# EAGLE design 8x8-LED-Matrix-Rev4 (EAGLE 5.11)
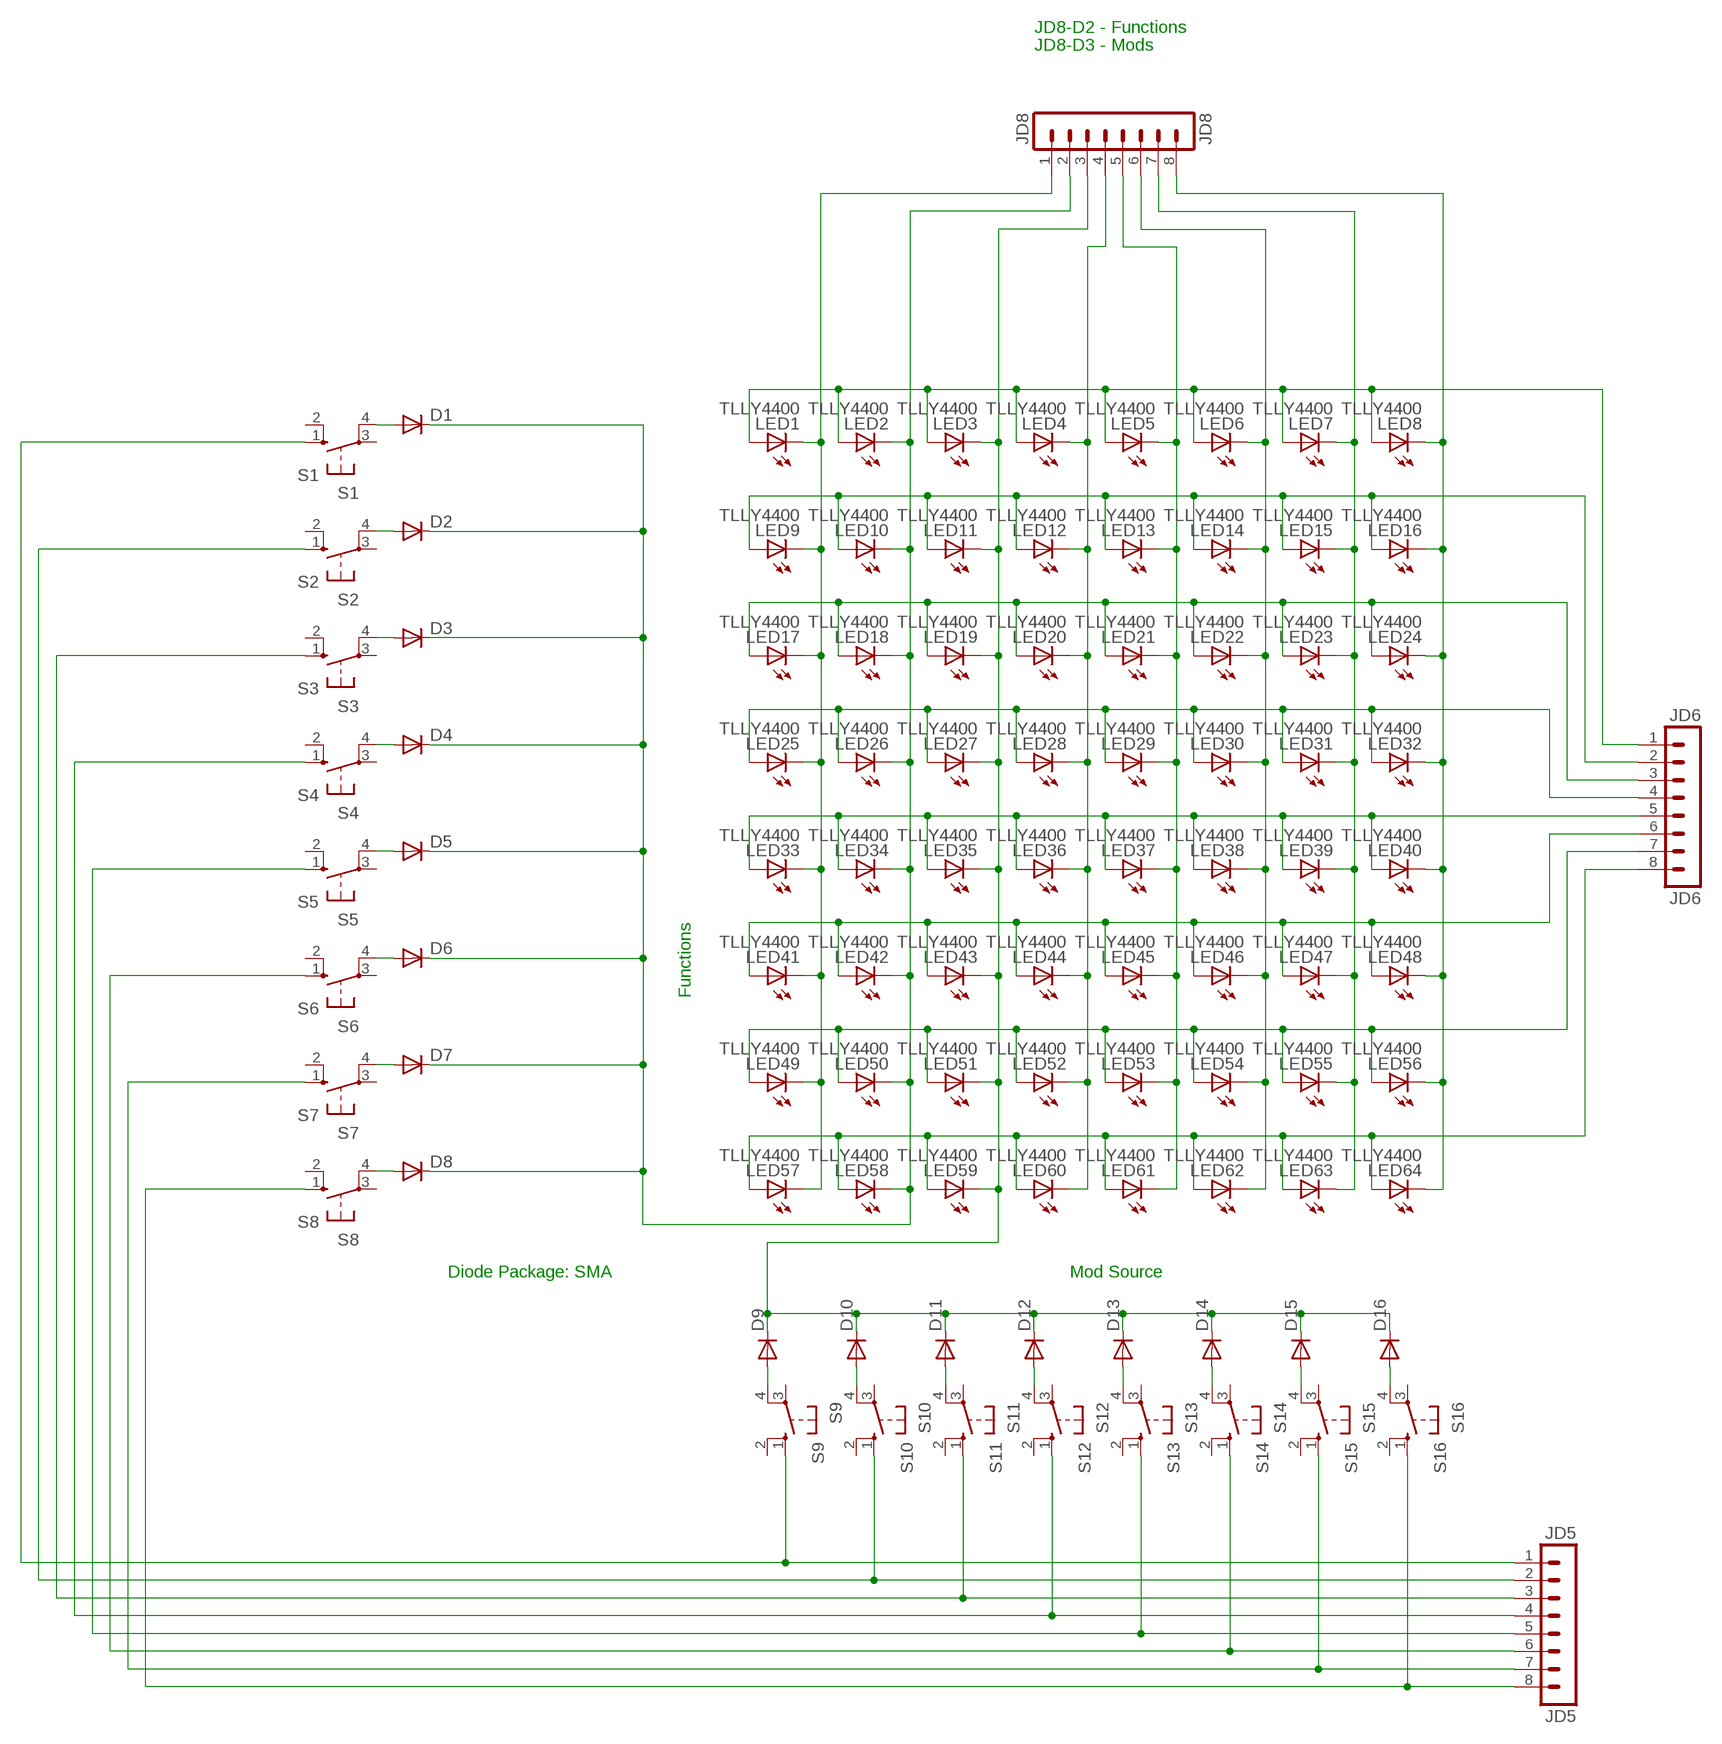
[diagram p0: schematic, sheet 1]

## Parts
D1  DIODE-DO214AC  [DO214AC]
D2  DIODE-DO214AC  [DO214AC]
D3  DIODE-DO214AC  [DO214AC]
D4  DIODE-DO214AC  [DO214AC]
D5  DIODE-DO214AC  [DO214AC]
D6  DIODE-DO214AC  [DO214AC]
D7  DIODE-DO214AC  [DO214AC]
D8  DIODE-DO214AC  [DO214AC]
D9  DIODE-DO214AC  [DO214AC]
D10  DIODE-DO214AC  [DO214AC]
D11  DIODE-DO214AC  [DO214AC]
D12  DIODE-DO214AC  [DO214AC]
D13  DIODE-DO214AC  [DO214AC]
D14  DIODE-DO214AC  [DO214AC]
D15  DIODE-DO214AC  [DO214AC]
D16  DIODE-DO214AC  [DO214AC]
JD5  JD5  MA08-1  [MA08-1]
JD6  JD6  MA08-1  [MA08-1]
JD8  JD8  MA08-1  [MA08-1]
LED1  TLLY4400  [LED3MM]
LED2  TLLY4400  [LED3MM]
LED3  TLLY4400  [LED3MM]
LED4  TLLY4400  [LED3MM]
LED5  TLLY4400  [LED3MM]
LED6  TLLY4400  [LED3MM]
LED7  TLLY4400  [LED3MM]
LED8  TLLY4400  [LED3MM]
LED9  TLLY4400  [LED3MM]
LED10  TLLY4400  [LED3MM]
LED11  TLLY4400  [LED3MM]
LED12  TLLY4400  [LED3MM]
LED13  TLLY4400  [LED3MM]
LED14  TLLY4400  [LED3MM]
LED15  TLLY4400  [LED3MM]
LED16  TLLY4400  [LED3MM]
LED17  TLLY4400  [LED3MM]
LED18  TLLY4400  [LED3MM]
LED19  TLLY4400  [LED3MM]
LED20  TLLY4400  [LED3MM]
LED21  TLLY4400  [LED3MM]
LED22  TLLY4400  [LED3MM]
LED23  TLLY4400  [LED3MM]
LED24  TLLY4400  [LED3MM]
LED25  TLLY4400  [LED3MM]
LED26  TLLY4400  [LED3MM]
LED27  TLLY4400  [LED3MM]
LED28  TLLY4400  [LED3MM]
LED29  TLLY4400  [LED3MM]
LED30  TLLY4400  [LED3MM]
LED31  TLLY4400  [LED3MM]
LED32  TLLY4400  [LED3MM]
LED33  TLLY4400  [LED3MM]
LED34  TLLY4400  [LED3MM]
LED35  TLLY4400  [LED3MM]
LED36  TLLY4400  [LED3MM]
LED37  TLLY4400  [LED3MM]
LED38  TLLY4400  [LED3MM]
LED39  TLLY4400  [LED3MM]
LED40  TLLY4400  [LED3MM]
LED41  TLLY4400  [LED3MM]
LED42  TLLY4400  [LED3MM]
LED43  TLLY4400  [LED3MM]
LED44  TLLY4400  [LED3MM]
LED45  TLLY4400  [LED3MM]
LED46  TLLY4400  [LED3MM]
LED47  TLLY4400  [LED3MM]
LED48  TLLY4400  [LED3MM]
LED49  TLLY4400  [LED3MM]
LED50  TLLY4400  [LED3MM]
LED51  TLLY4400  [LED3MM]
LED52  TLLY4400  [LED3MM]
LED53  TLLY4400  [LED3MM]
LED54  TLLY4400  [LED3MM]
LED55  TLLY4400  [LED3MM]
LED56  TLLY4400  [LED3MM]
LED57  TLLY4400  [LED3MM]
LED58  TLLY4400  [LED3MM]
LED59  TLLY4400  [LED3MM]
LED60  TLLY4400  [LED3MM]
LED61  TLLY4400  [LED3MM]
LED62  TLLY4400  [LED3MM]
LED63  TLLY4400  [LED3MM]
LED64  TLLY4400  [LED3MM]
S1  S1  10-XX  [B3F-10XX]
S2  S2  10-XX  [B3F-10XX]
S3  S3  10-XX  [B3F-10XX]
S4  S4  10-XX  [B3F-10XX]
S5  S5  10-XX  [B3F-10XX]
S6  S6  10-XX  [B3F-10XX]
S7  S7  10-XX  [B3F-10XX]
S8  S8  10-XX  [B3F-10XX]
S9  S9  10-XX  [B3F-10XX]
S10  S10  10-XX  [B3F-10XX]
S11  S11  10-XX  [B3F-10XX]
S12  S12  10-XX  [B3F-10XX]
S13  S13  10-XX  [B3F-10XX]
S14  S14  10-XX  [B3F-10XX]
S15  S15  10-XX  [B3F-10XX]
S16  S16  10-XX  [B3F-10XX]

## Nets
N$1: JD6.1 LED1.A LED2.A LED3.A LED4.A LED5.A LED6.A LED7.A LED8.A
N$2: JD6.2 LED9.A LED10.A LED11.A LED12.A LED13.A LED14.A LED15.A LED16.A
N$3: JD6.3 LED17.A LED18.A LED19.A LED20.A LED21.A LED22.A LED23.A LED24.A
N$4: JD6.4 LED25.A LED26.A LED27.A LED28.A LED29.A LED30.A LED31.A LED32.A
N$5: JD6.5 LED33.A LED34.A LED35.A LED36.A LED37.A LED38.A LED39.A LED40.A
N$6: JD6.6 LED41.A LED42.A LED43.A LED44.A LED45.A LED46.A LED47.A LED48.A
N$7: D1.A S1.4(P1)
N$8: JD6.8 LED57.A LED58.A LED59.A LED60.A LED61.A LED62.A LED63.A LED64.A
N$9: JD8.1 LED1.K(C) LED9.K(C) LED17.K(C) LED25.K(C) LED33.K(C) LED41.K(C) LED49.K(C) LED57.K(C)
N$10: D1.C D2.C D3.C D4.C D5.C D6.C D7.C D8.C JD8.2 LED2.K(C) LED10.K(C) LED18.K(C) LED26.K(C) LED34.K(C) LED42.K(C) LED50.K(C) LED58.K(C)
N$11: D2.A S2.4(P1)
N$12: JD8.4 LED4.K(C) LED12.K(C) LED20.K(C) LED28.K(C) LED36.K(C) LED44.K(C) LED52.K(C) LED60.K(C)
N$13: JD8.5 LED5.K(C) LED13.K(C) LED21.K(C) LED29.K(C) LED37.K(C) LED45.K(C) LED53.K(C) LED61.K(C)
N$14: JD8.6 LED6.K(C) LED14.K(C) LED22.K(C) LED30.K(C) LED38.K(C) LED46.K(C) LED54.K(C) LED62.K(C)
N$15: JD8.7 LED7.K(C) LED15.K(C) LED23.K(C) LED31.K(C) LED39.K(C) LED47.K(C) LED55.K(C) LED63.K(C)
N$16: JD8.8 LED8.K(C) LED16.K(C) LED24.K(C) LED32.K(C) LED40.K(C) LED48.K(C) LED56.K(C) LED64.K(C)
N$17: JD6.7 LED49.A LED50.A LED51.A LED52.A LED53.A LED54.A LED55.A LED56.A
N$18: JD5.1 S1.1(S) S9.1(S)
N$19: JD5.2 S2.1(S) S10.1(S)
N$20: JD5.4 S4.1(S) S12.1(S)
N$21: JD5.5 S5.1(S) S13.1(S)
N$22: JD5.6 S6.1(S) S14.1(S)
N$23: JD5.7 S7.1(S) S15.1(S)
N$24: JD5.8 S8.1(S) S16.1(S)
N$25: JD5.3 S3.1(S) S11.1(S)
N$26: D3.A S3.4(P1)
N$27: D4.A S4.4(P1)
N$28: D5.A S5.4(P1)
N$29: D6.A S6.4(P1)
N$30: D7.A S7.4(P1)
N$31: D9.C D10.C D11.C D12.C D13.C D14.C D15.C D16.C JD8.3 LED3.K(C) LED11.K(C) LED19.K(C) LED27.K(C) LED35.K(C) LED43.K(C) LED51.K(C) LED59.K(C)
N$32: D9.A S9.4(P1)
N$33: D10.A S10.4(P1)
N$34: D8.A S8.4(P1)
N$35: D11.A S11.4(P1)
N$36: D12.A S12.4(P1)
N$37: D13.A S13.4(P1)
N$38: D14.A S14.4(P1)
N$39: D15.A S15.4(P1)
N$40: D16.A S16.4(P1)
Unconnected: S1.2(S1) S1.3(P) S2.2(S1) S2.3(P) S3.2(S1) S3.3(P) S4.2(S1) S4.3(P) S5.2(S1) S5.3(P) S6.2(S1) S6.3(P) S7.2(S1) S7.3(P) S8.2(S1) S8.3(P) S9.2(S1) S9.3(P) S10.2(S1) S10.3(P) S11.2(S1) S11.3(P) S12.2(S1) S12.3(P) S13.2(S1) S13.3(P) S14.2(S1) S14.3(P) S15.2(S1) S15.3(P) S16.2(S1) S16.3(P)

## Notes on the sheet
- JD8-D2 - Functions
- JD8-D3 - Mods
- Functions
- Diode Package: SMA | Mod Source

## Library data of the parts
D1-D16 = diode:DIODE-: DIODE
JD5 JD6 JD8 = con-lstb:MA08-1: PIN HEADER; OC_FARNELL: unknown; OC_NEWARK: unknown
LED1-LED64 = led:TLLY4400: Low Current (2mA) LED 3 mm Tinted Diffused Package color YELLOW; MF: VISHAY SEMICONDUCTOR; OC_FARNELL: 1612439
S1-S16 = switch-omron:10-XX: OMRON SWITCH; MPN: B3F-1000; OC_FARNELL: 176432; OC_NEWARK: 36M3542

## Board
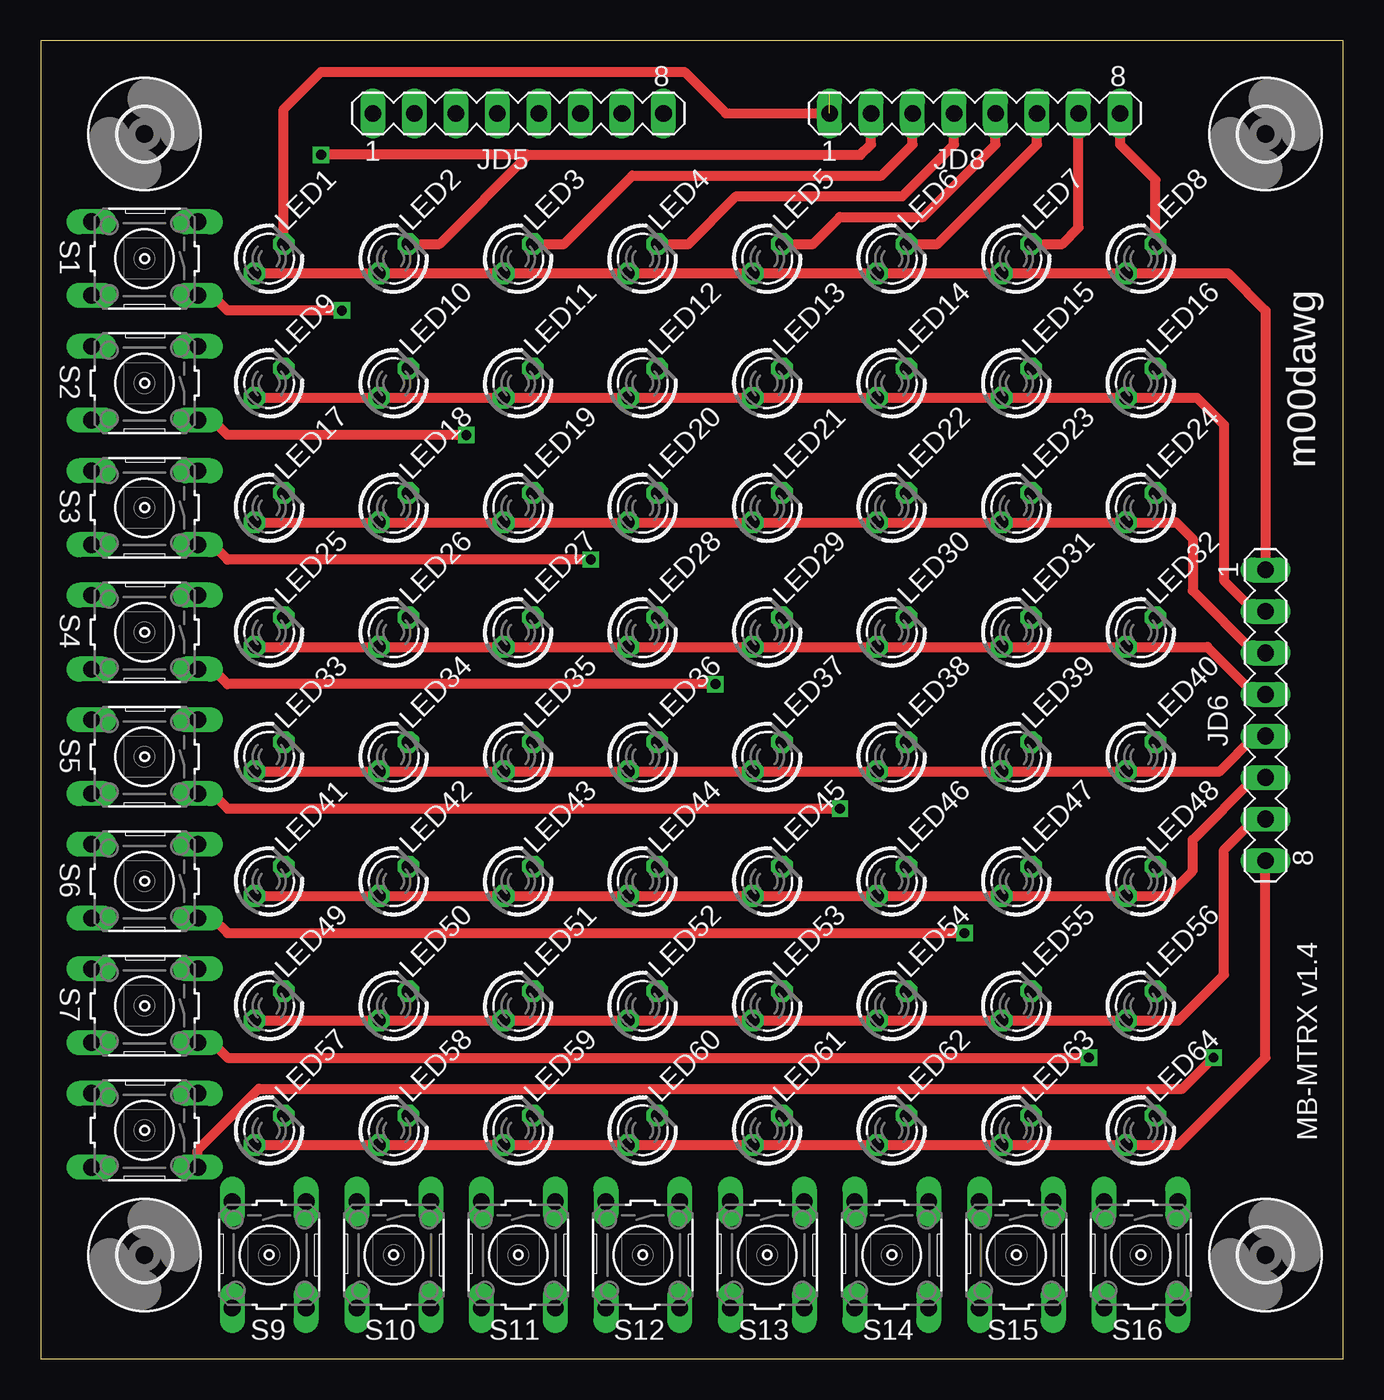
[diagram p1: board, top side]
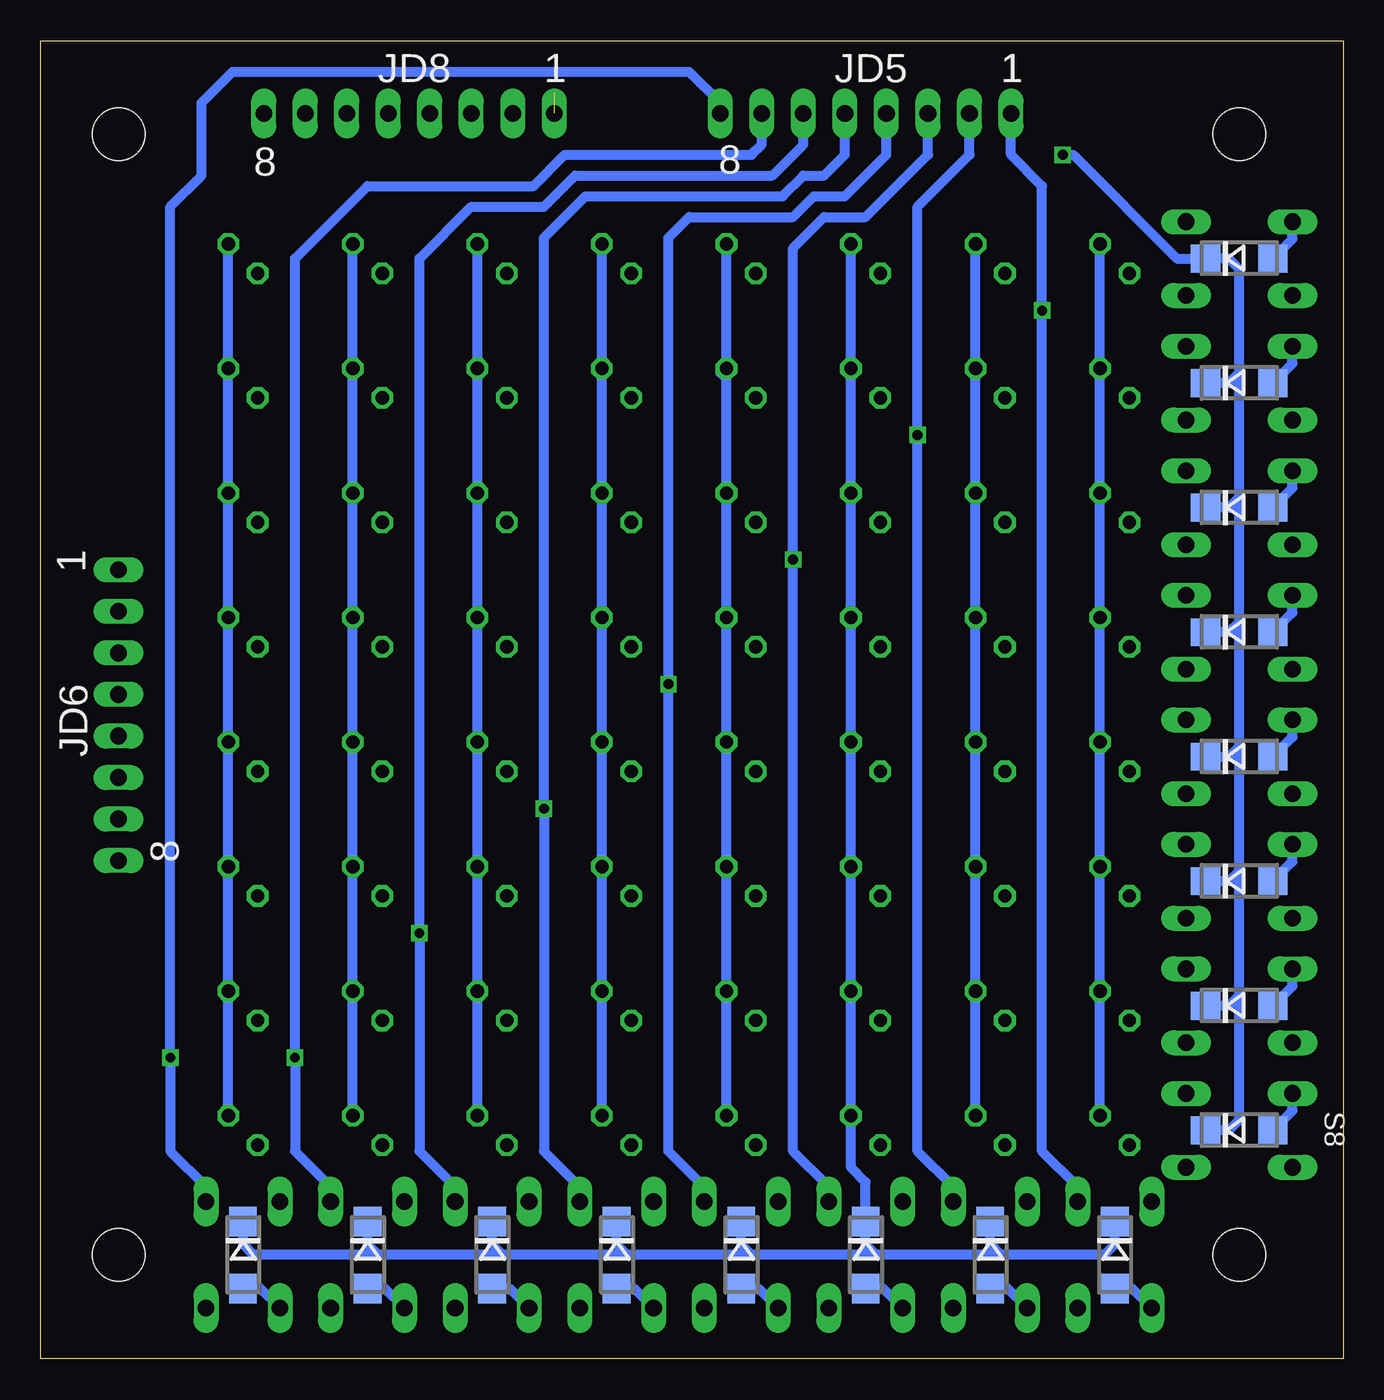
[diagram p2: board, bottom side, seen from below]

Size 79.68 x 80.64 mm. Coordinates in mm from the lower left corner, seen from the top.
Outline: 0,0 79.68,0 79.68,80.64 0,80.64 0,0
Copper layers (1*16): Top 0.035mm / dielectric 1.5mm / Bottom 0.035mm
Design rules "batchpcb": minimum track width 8mil, minimum drill 20mil, track to track 8mil, track to pad 8mil, pad to pad 8mil, via to via 8mil, smd to smd 8mil, copper to edge 40mil, drill to drill 8mil, minimum pad ring 10mil, minimum via ring 8mil, stop-mask expansion 4mil, vias tented up to drill 0mil, thermal gap 10mil

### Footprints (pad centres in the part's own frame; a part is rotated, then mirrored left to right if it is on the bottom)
DO214AC = smd 1.8 x 1.7: A 2.05,0; C -2.05,0
MA08-1 = drill 1.016 long: 1 -8.89,0; 2 -6.35,0; 3 -3.81,0; 4 -1.27,0; 5 1.27,0; 6 3.81,0; 7 6.35,0; 8 8.89,0
LED3MM = drill 0.813 octagon: A -1.27,0; K 1.27,0
B3F-10XX = drill 1.016 long: 1 -3.251,2.261; 2 3.251,2.261; 3 -3.251,-2.261; 4 3.251,-2.261
3,2 = hole 3.2: 0,0

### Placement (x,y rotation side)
D1  6.35,67.31 0 bottom
D2  6.35,59.69 0 bottom
D3  6.35,52.07 0 bottom
D4  6.35,44.45 0 bottom
D5  6.35,36.83 0 bottom
D6  6.35,29.21 0 bottom
D7  6.35,21.59 0 bottom
D8  6.35,13.97 0 bottom
D9  13.97,6.35 270 bottom
D10  21.59,6.35 270 bottom
D11  29.21,6.35 270 bottom
D12  36.83,6.35 270 bottom
D13  44.45,6.35 270 bottom
D14  52.07,6.35 270 bottom
D15  59.69,6.35 270 bottom
D16  67.31,6.35 270 bottom
JD5  29.21,76.2 0 top
JD6  74.93,39.37 270 top
JD8  57.15,76.2 0 top
LED1  13.97,67.31 45 top
LED2  21.59,67.31 45 top
LED3  29.21,67.31 45 top
LED4  36.83,67.31 45 top
LED5  44.45,67.31 45 top
LED6  52.07,67.31 45 top
LED7  59.69,67.31 45 top
LED8  67.31,67.31 45 top
LED9  13.97,59.69 45 top
LED10  21.59,59.69 45 top
LED11  29.21,59.69 45 top
LED12  36.83,59.69 45 top
LED13  44.45,59.69 45 top
LED14  52.07,59.69 45 top
LED15  59.69,59.69 45 top
LED16  67.31,59.69 45 top
LED17  13.97,52.07 45 top
LED18  21.59,52.07 45 top
LED19  29.21,52.07 45 top
LED20  36.83,52.07 45 top
LED21  44.45,52.07 45 top
LED22  52.07,52.07 45 top
LED23  59.69,52.07 45 top
LED24  67.31,52.07 45 top
LED25  13.97,44.45 45 top
LED26  21.59,44.45 45 top
LED27  29.21,44.45 45 top
LED28  36.83,44.45 45 top
LED29  44.45,44.45 45 top
LED30  52.07,44.45 45 top
LED31  59.69,44.45 45 top
LED32  67.31,44.45 45 top
LED33  13.97,36.83 45 top
LED34  21.59,36.83 45 top
LED35  29.21,36.83 45 top
LED36  36.83,36.83 45 top
LED37  44.45,36.83 45 top
LED38  52.07,36.83 45 top
LED39  59.69,36.83 45 top
LED40  67.31,36.83 45 top
LED41  13.97,29.21 45 top
LED42  21.59,29.21 45 top
LED43  29.21,29.21 45 top
LED44  36.83,29.21 45 top
LED45  44.45,29.21 45 top
LED46  52.07,29.21 45 top
LED47  59.69,29.21 45 top
LED48  67.31,29.21 45 top
LED49  13.97,21.59 45 top
LED50  21.59,21.59 45 top
LED51  29.21,21.59 45 top
LED52  36.83,21.59 45 top
LED53  44.45,21.59 45 top
LED54  52.07,21.59 45 top
LED55  59.69,21.59 45 top
LED56  67.31,21.59 45 top
LED57  13.97,13.97 45 top
LED58  21.59,13.97 45 top
LED59  29.21,13.97 45 top
LED60  36.83,13.97 45 top
LED61  44.45,13.97 45 top
LED62  52.07,13.97 45 top
LED63  59.69,13.97 45 top
LED64  67.31,13.97 45 top
S1  6.35,67.31 180 top
S2  6.35,59.69 180 top
S3  6.35,52.07 180 top
S4  6.35,44.45 180 top
S5  6.35,36.83 180 top
S6  6.35,29.21 180 top
S7  6.35,21.59 180 top
S8  6.35,13.97 180 top
S9  13.97,6.35 270 top
S10  21.59,6.35 270 top
S11  29.21,6.35 270 top
S12  36.83,6.35 270 top
S13  44.45,6.35 270 top
S14  52.07,6.35 270 top
S15  59.69,6.35 270 top
S16  67.31,6.35 270 top
U$1  [3,2]  6.35,74.93 0 top
U$2  [3,2]  74.93,74.93 0 top
U$3  [3,2]  74.93,6.35 0 top
U$4  [3,2]  6.35,6.35 0 top

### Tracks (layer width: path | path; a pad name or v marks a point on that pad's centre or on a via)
N$1
  Top 0.61: JD6.1 74.93,64.14 72.65,66.41 LED8.A LED7.A LED6.A LED5.A LED4.A LED3.A LED2.A LED1.A
N$2
  Top 0.61: JD6.2 74.3,45.72 72.39,47.62 72.39,57.15 70.75,58.79 LED16.A LED15.A LED14.A LED13.A LED12.A LED11.A LED10.A LED9.A
N$3
  Top 0.61: JD6.3 74.3,43.18 70.48,46.99 70.48,50.16 69.48,51.17 LED24.A LED23.A LED22.A LED21.A LED20.A LED19.A LED18.A LED17.A
N$4
  Top 0.61: JD6.4 74.3,40.64 71.38,43.55 LED32.A LED31.A LED30.A LED29.A LED28.A LED27.A LED26.A LED25.A
N$5
  Top 0.61: JD6.5 74.3,38.1 72.13,35.93 LED40.A LED39.A LED38.A LED37.A LED36.A LED35.A LED34.A LED33.A
N$6
  Top 0.61: JD6.6 74.3,35.56 70.48,31.75 70.48,29.84 68.95,28.31 LED48.A LED47.A LED46.A LED45.A LED44.A LED43.A LED42.A LED41.A
N$7
  Bottom 0.61: S1.4 3.1,68.51 D1.A
N$8
  Top 0.61: JD6.8 74.93,18.41 69.59,13.07 LED64.A LED63.A LED62.A LED61.A LED60.A LED59.A LED58.A LED57.A
N$9  (1 unrouted)
  Top 0.61: LED1.K 14.87,76.46 17.14,78.74 39.37,78.74 41.91,76.2 JD8.1
  Bottom 0.61: LED1.K LED9.K LED17.K LED25.K LED33.K LED41.K LED49.K LED57.K
N$10  (via drill 0.6)
  Top 0.61: LED2.K 24.39,68.21 29.84,73.66 | 29.84,73.66 50.16,73.66 50.8,74.3 JD8.2 | 29.84,73.66 v17.14,73.66
  Bottom 0.61: LED2.K LED10.K LED18.K LED26.K LED34.K LED42.K LED50.K LED58.K | v17.14,73.66 16.51,73.66 10.16,67.31 D1.C 6.99,67.31 6.35,66.67 6.35,60.33 | 6.35,22.23 6.35,29.84 | 6.35,29.84 6.35,37.47 | 6.35,37.47 6.35,45.09 | 6.35,45.09 6.35,52.7 | 6.35,52.7 6.35,60.33 | 6.35,22.23 6.99,21.59 D7.C | D6.C 6.99,29.21 6.35,29.84 | D5.C 6.99,36.83 6.35,37.47 | D4.C 6.99,44.45 6.35,45.09 | D3.C 6.99,52.07 6.35,52.7 | D2.C 6.99,59.69 6.35,60.33 | D8.C 6.99,13.97 6.35,14.61 6.35,22.23
N$11
  Bottom 0.61: S2.4 3.1,60.89 D2.A
N$12
  Top 0.61: JD8.4 55.88,74.3 52.7,71.12 42.55,71.12 39.63,68.21 LED4.K
  Bottom 0.61: LED4.K LED12.K 37.99,60.33 38.1,60.33 37.73,59.95 LED20.K LED28.K LED36.K LED44.K LED52.K LED60.K
N$13
  Top 0.61: JD8.5 58.42,74.3 53.98,69.85 48.9,69.85 47.25,68.21 LED5.K
  Bottom 0.61: LED5.K LED13.K LED21.K LED29.K LED37.K LED45.K LED53.K LED61.K
N$14
  Top 0.61: LED6.K 54.87,68.21 60.96,74.3 JD8.6
  Bottom 0.61: LED6.K LED14.K LED22.K LED30.K LED38.K LED46.K LED54.K LED62.K
N$15
  Top 0.61: LED7.K 62.49,68.21 63.5,69.22 JD8.7
  Bottom 0.61: LED7.K LED15.K LED23.K LED31.K LED39.K LED47.K LED55.K LED63.K
N$16
  Top 0.61: JD8.8 66.04,74.3 68.21,72.13 LED8.K
  Bottom 0.61: LED8.K LED16.K LED24.K LED32.K LED40.K LED48.K LED56.K LED64.K
N$17
  Top 0.61: JD6.7 74.3,33.02 72.39,31.11 72.39,23.5 69.59,20.69 LED56.A LED55.A LED54.A LED53.A LED52.A LED51.A LED50.A LED49.A
N$18  (via drill 0.6)
  Top 0.61: S1.1 10.52,65.05 11.43,64.14 v18.41,64.14
  Bottom 0.61: S9.1 16.23,10.52 18.41,12.7 v18.41,64.14 18.41,71.75 20.32,73.66 JD5.1
N$19  (via drill 0.6)
  Top 0.61: S2.1 10.52,57.43 11.43,56.52 v26.04,56.52
  Bottom 0.61: S10.1 23.85,10.52 26.04,12.7 v26.04,56.52 26.04,70.48 22.86,73.66 JD5.2
N$20  (via drill 0.6)
  Top 0.61: S4.1 10.52,42.19 11.43,41.27 v41.27,41.27
  Bottom 0.61: S12.1 39.09,10.52 41.27,12.7 v41.27,41.27 41.27,68.58 40.01,69.85 33.66,69.85 32.38,71.12 30.48,71.12 27.94,73.66 JD5.4
N$21  (via drill 0.6)
  Top 0.61: S5.1 10.52,34.57 11.43,33.66 v48.9,33.66
  Bottom 0.61: S13.1 46.71,10.52 48.9,12.7 v48.9,33.66 48.9,68.58 46.35,71.12 34.29,71.12 33.02,72.39 31.75,72.39 30.48,73.66 JD5.5
N$22  (via drill 0.6)
  Top 0.61: S6.1 10.52,26.95 11.43,26.04 v56.52,26.04
  Bottom 0.61: S14.1 54.33,10.52 56.52,12.7 v56.52,26.04 56.52,67.31 53.34,70.48 48.9,70.48 46.99,72.39 34.92,72.39 33.02,74.3 JD5.6
N$23  (via drill 0.6)
  Top 0.61: S7.1 10.52,19.33 11.43,18.41 v64.14,18.41
  Bottom 0.61: S15.1 61.95,10.52 64.14,12.7 v64.14,18.41 64.14,67.31 59.69,71.75 49.53,71.75 47.62,73.66 36.2,73.66 35.56,74.3 JD5.7
N$24  (via drill 0.6)
  Top 0.61: S8.1 9.6,12.78 13.34,16.51 69.85,16.51 v71.75,18.41
  Bottom 0.61: S16.1 69.57,10.52 71.75,12.7 v71.75,18.41 71.75,70.48 69.85,72.39 69.85,76.83 67.94,78.74 40.01,78.74 38.1,76.83 JD5.8
N$25  (via drill 0.6)
  Top 0.61: S3.1 10.52,49.81 11.43,48.9 v33.66,48.9
  Bottom 0.61: S11.1 31.47,10.52 33.66,12.7 v33.66,48.9 33.66,67.94 31.75,69.85 29.21,69.85 25.4,73.66 JD5.3
N$26
  Bottom 0.61: S3.4 3.1,53.27 D3.A
N$27
  Bottom 0.61: S4.4 3.1,45.65 D4.A
N$28
  Bottom 0.61: S5.4 3.1,38.03 D5.A
N$29
  Bottom 0.61: S6.4 3.1,30.41 D6.A
N$30
  Bottom 0.61: S7.4 3.1,22.79 D7.A
N$31
  Top 0.61: LED3.K 32.01,68.21 36.2,72.39 51.44,72.39 53.34,74.3 JD8.3
  Bottom 0.61: LED3.K LED11.K LED19.K LED27.K LED35.K LED43.K LED51.K LED59.K 30.11,11.69 29.21,10.79 D11.C 29.21,6.99 28.57,6.35 | D9.C 13.97,6.99 14.61,6.35 20.95,6.35 | 20.95,6.35 28.57,6.35 | 28.57,6.35 36.2,6.35 | 36.2,6.35 43.81,6.35 | 43.81,6.35 51.44,6.35 | 51.44,6.35 59.05,6.35 | 59.05,6.35 66.67,6.35 67.31,6.99 D16.C | D15.C 59.69,6.99 59.05,6.35 | D14.C 52.07,6.99 51.44,6.35 | D13.C 44.45,6.99 43.81,6.35 | D12.C 36.83,6.99 36.2,6.35 | D10.C 21.59,6.99 20.95,6.35
N$32
  Bottom 0.61: D9.A 12.91,4.3 S9.4
N$33
  Bottom 0.61: D10.A 20.53,4.3 S10.4
N$34
  Bottom 0.61: S8.4 3.1,15.17 D8.A
N$35
  Bottom 0.61: D11.A 28.15,4.3 S11.4
N$36
  Bottom 0.61: D12.A 35.77,4.3 S12.4
N$37
  Bottom 0.61: D13.A 43.39,4.3 S13.4
N$38
  Bottom 0.61: D14.A 51.01,4.3 S14.4
N$39
  Bottom 0.61: D15.A 58.63,4.3 S15.4
N$40
  Bottom 0.61: D16.A 66.25,4.3 S16.4

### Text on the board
tPlace: m00dawg | MB-MTRX v1.4
bPlace: 1 | JD5 | 1 | JD8 | 8 | 8 | 1 | JD6 | 8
